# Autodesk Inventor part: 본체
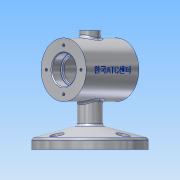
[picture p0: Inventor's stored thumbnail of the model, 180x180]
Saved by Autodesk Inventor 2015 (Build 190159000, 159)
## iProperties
Created: 2018-12
Part Number: 본체
Material: 알루미늄 6061
Document SubType Name: Modeling
Designer: 405-10
Density: 2.7 g/cm^3
Appearance: 알루미늄 - 평지
Mass: 685.082 g
Surface Area: 555.474 cm^2
Volume: 253.734 cm^3
Author: 405-10
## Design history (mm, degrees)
sketch "스케치1"
  geometry: C1 r 55 at (0, 0); 1 further point
  constraints: 1 centre point, 1 coincident
  dimensions: "d0" = 110 diameter of C1
extrude "돌출1" new body sketch "스케치1" distance "d1" = 11; taper "d2" = 0 deg
sketch "스케치2"
  geometry: L1 (0, 25.737)-(55, 11); L2 (55, 0)-(55, 11) reference; L3 (55, 11)-(0, 11); L4 (55, 11)-(-55, 11) reference; L5 (0, 11)-(0, 25.737); 1 further point
  constraints: 6 end point, 1 midpoint, 1 vertical
  dimensions: "d3" = 75 deg angle of L2 L1
revolve "회전1" sketch "스케치2" stored, may be unused: angle "d4" = 90 deg
sketch "스케치3"
  geometry: L1 (-55, 0)-(55, 0) reference; C1 r 30 at (0, 75); 1 further point
  constraints: 1 centre point, 1 vertical alignment
  dimensions: "d6" = 60 diameter of C1; "d7" = 75 distance from line of L1 C1.centre
extrude "돌출2" join sketch "스케치3" stored distance "d8" = 70; taper "d9" = 0 deg
node "작업 평면3"
  node "작업 평면2"
sketch "스케치4"
  geometry: C1 r 12 at (0, 0); 1 further point
  constraints: 1 centre point, 1 coincident
  dimensions: "d11" = 24 diameter of C1
extrude "돌출3" join sketch "스케치4" stored distance "d12" = 70; taper "d13" = 0 deg
sketch "스케치5"
  geometry: C1 r 30 at (0, 0) reference; C2 r 16 at (0, 0); 1 further point
  constraints: 1 centre point, 1 coincident
  dimensions: "d14" = 32 diameter of C2
extrude "돌출4" cut sketch "스케치5" distance "d15" = 12; taper "d16" = 0 deg
sketch "스케치6"
  geometry: C1 r 16 at (0, 0) reference; C2 r 14 at (0, 0); 1 further point
  constraints: 1 centre point, 1 coincident
  dimensions: "d17" = 28 diameter of C2
extrude "돌출5" cut sketch "스케치6" distance "d18" = 3; taper "d19" = 0 deg
sketch "스케치10"
  geometry: C1 r 30 at (0, 0) reference; C2 r 25 at (0, 0); 1 further point
  constraints: 1 centre point, 1 coincident
  dimensions: "d30" = 50 diameter of C2
extrude "돌출8" cut sketch "스케치10" distance "d31" = 40; taper "d32" = 0 deg
node "작업 평면4"
sketch "스케치11"
  geometry: C1 r 12 at (0, 0) reference; C2 r 10 at (0, 0); 1 further point
  constraints: 1 centre point, 1 coincident
  dimensions: "d34" = 20 diameter of C2
extrude "돌출9" join sketch "스케치11" stored distance "d35" = 10; taper "d36" = 0 deg
hole "구멍1" diameter "d39" = 10; stored, may be unused: countersink angle "d43" = 90 deg, drill point angle "d45" = 0 deg; dims "d37" = 10, "d38" = 10, "d40" = 6, "d41" = 4, "d42" = 2, "d44" = 30
sketch "스케치12" dims "d46" = 46
  geometry: C1 r 30 at (0, 0) reference; 3 further points
  constraints: 2 vertical alignment, 1 coincident, 2 other
hole "구멍2" sketch "스케치12" at (0, 23) diameter "d47" = 3.242; stored, may be unused: countersink angle "d51" = 90 deg, drill point angle "d53" = 118 deg; dims "d48" = 8, "d49" = 4, "d50" = 2, "d52" = 10
sketch "스케치14" dims "d57" = 88
  geometry: 3 further points
  constraints: 2 horizontal alignment, 1 coincident, 2 other
hole "구멍3" sketch "스케치14" at (44, 0) diameter "d58" = 9; stored, may be unused: countersink angle "d62" = 90 deg, drill point angle "d64" = 0 deg; dims "d59" = 8, "d60" = 4, "d61" = 2, "d63" = 10
sketch "스케치15"
  geometry: C1 r 4.5 at (0, 0) reference; C2 r 7 at (0, 0); 1 further point
  constraints: 1 centre point, 1 coincident
  dimensions: "d65" = 14 diameter of C2
extrude "돌출10" cut sketch "스케치15" distance "d66" = 10; taper "d67" = 0 deg
node "작업 평면6"
  node "작업 평면5"
sketch "스케치16"
  geometry: L1 (30, 35)-(-30, 35) reference; 2 further points
  constraints: 1 other
  dimensions: "d72" = 35 distance from line of L1 point (0, 0); "d73" = 30 horizontal distance of L1.start point (0, 0)
feature "엠보싱1" sketch "스케치16" dims "d74" = 0.5, "d75" = 0
fillet "모깎기1" dims "d76" = 3
fillet "모깎기2" dims "d77" = 3
chamfer "모따기1" distance "d78" = 1; stored, may be unused: second distance "d79" = 2, angle "d80" = 45 deg
fillet "모깎기3" dims "d81" = 0.3
node "솔리드1"
mirror "대칭1"
pattern_circular "원형 패턴1" dims angle "d55" = 360 deg
mirror "대칭2"
pattern_circular "원형 패턴2" dims angle "d69" = 360 deg
other parameters: "d33" = 112
